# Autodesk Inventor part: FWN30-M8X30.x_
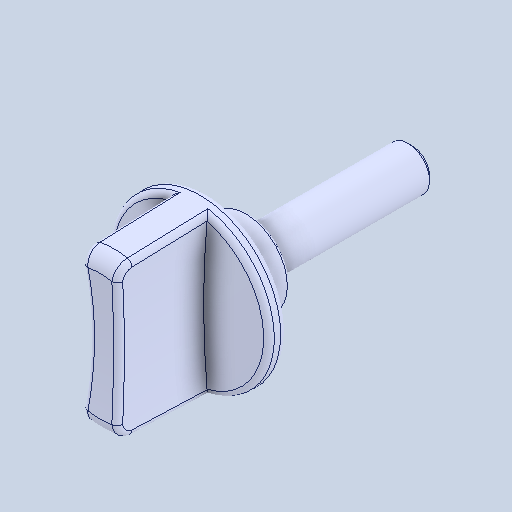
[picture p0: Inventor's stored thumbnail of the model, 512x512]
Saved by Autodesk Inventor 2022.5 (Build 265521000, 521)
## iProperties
Created: 2024-05
Part Number: FWN30-M8X30.x_
Material: 一般
Document SubType Name: Modeling
Designer: ImaoCorp
Density: 1 g/cm^3
Appearance: 既定
Author: ImaoCorp
Sending System: SOLIDWORKS 2022-2022290
MC: AMD64
MC_MODEL: Intel64 Family 6 Model 60 Stepping 3, GenuineIntel
OS: Windows_NT
FRU: Parasolid Version 33.1, build 260,  4-25-2022
FORMAT: text
GUISE: transmit
KEY: FILEFWN30-M8X30.x_t
DATE: Mon May 20 16:40:24 2024
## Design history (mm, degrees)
feature "Base1"
node "ソリッド1"
